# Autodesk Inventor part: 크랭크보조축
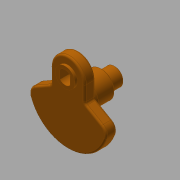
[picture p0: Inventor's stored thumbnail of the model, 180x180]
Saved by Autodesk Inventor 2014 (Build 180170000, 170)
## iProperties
Created: 2016-11
Part Number: 크랭크보조축
Material: 강철, 탄소
Document SubType Name: Modeling
Designer: mduedu
Density: 7.87 g/cm^3
Appearance: 주황색
Mass: 629.242 g
Surface Area: 163.688 cm^2
Volume: 79.9545 cm^3
Author: mduedu
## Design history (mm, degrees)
sketch "스케치1" dims "d8" = 65
  geometry: L1 (-19, 26.368)-(-19, 8.368); L2 (-19, 8.368)-(-44.545, -6.381); L3 (0, 26.368)-(0, -45); L4 (19, 26.368)-(19, 8.368); L5 (19, 8.368)-(44.545, -6.381); C1 r 10 at (0, 0); C2 r 17.5 at (0, 0); A1 r 45 centre (0, 0) between (-44.545, -6.381) and (0, -45); A2 r 19 centre (0, 26.368) between (0, 45.368) and (-19, 26.368); A3 r 19 centre (0, 26.368) between (19, 26.368) and (0, 45.368); A4 r 45 centre (0, 0) between (0, -45) and (44.545, -6.381); 2 further points
  constraints: 10 end point, 8 point on circle, 6 centre point, 4 coincident, 3 symmetric about line, 2 point on line, 1 parallel, 1 tangent, 1 vertical, 1 vertical alignment, 5 other
  dimensions: "d1" = 20 diameter of C1; "d2" = 35 diameter of C2; "d4" = 18 distance of L1.start L1.end; "d5" = 120 deg angle of L2 L1; "d6" = 45 radius of A1; "d9" = 19 radius of A2
extrude "돌출1" new body sketch "스케치1" distance "d10" = 12; taper "d11" = 0 deg
sketch "스케치2"
  geometry: C1 r 7.5 at (0, 26.368); C2 r 11 at (0, 26.368); A1 r 19 centre (0, 26.368) between (19, 26.368) and (-19, 26.368) reference; 1 further point
  constraints: 2 centre point, 2 coincident
  dimensions: "d16" = 15 diameter of C1; "d17" = 22 diameter of C2
extrude "돌출10" join sketch "스케치1" distance "d46" = 5; taper "d47" = 0 deg
extrude "돌출11" join sketch "스케치1" distance "d48" = 41; taper "d49" = 0 deg
extrude "돌출12" join sketch "스케치2" distance "d50" = 3; taper "d51" = 0 deg
extrude "돌출13" cut sketch "스케치2" stored distance "d52" = 3; taper "d53" = 0 deg
sketch "스케치7"
  geometry: L1 (5.75, -4.815)-(-5.75, -4.815); L2 (-5.75, -4.815)-(-5.75, 4.815); L3 (-5.75, 4.815)-(5.75, 4.815); L4 (5.75, 4.815)-(5.75, -4.815); L5 (5.75, -4.815)-(-5.75, 4.815); L6 (-5.75, -4.815)-(5.75, 4.815); A1 r 7.5 centre (0, 0) between (-5.75, 4.815) and (-5.75, -4.815); A2 r 7.5 centre (0, 0) between (5.75, -4.815) and (5.75, 4.815); 2 further points
  constraints: 12 end point, 4 point on circle, 2 centre point, 2 midpoint, 2 parallel, 1 coincident, 1 horizontal, 1 perpendicular, 2 other
  dimensions: "d54" = 11.5 distance of L2.end L3.end
extrude "돌출14" join sketch "스케치7" stored distance "d56" = 40.75; taper "d57" = 0 deg
sketch "스케치8"
  geometry: C1 r 17.5 at (0, 0) reference; C2 r 15 at (0, 0); 1 further point
  constraints: 1 centre point, 1 coincident
  dimensions: "d58" = 30 diameter of C2
extrude "돌출15" join sketch "스케치8" distance "d59" = 21; taper "d60" = 0 deg
chamfer "모따기3" distance "d61" = 1; stored, may be unused: second distance "d62" = 2, angle "d63" = 45 deg
fillet "모깎기3" dims "d64" = 3, "d65" = 10
fillet "모깎기4" dims "d66" = 2
node "솔리드1"
other parameters: "d3" = 38
